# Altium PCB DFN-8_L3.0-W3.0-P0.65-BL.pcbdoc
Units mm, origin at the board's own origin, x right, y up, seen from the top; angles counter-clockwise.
Board outline 15.8 x 16.8 mm, 2 copper layers (Top Layer, Bottom Layer), stack 0 mm thick; 1 components, 0 nets, 9 pads, 0 vias.
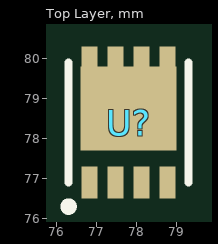
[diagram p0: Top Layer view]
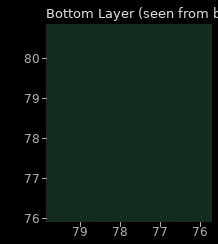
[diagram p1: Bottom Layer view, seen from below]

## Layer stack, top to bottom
Top Layer: signal copper (thickness not stored)
Bottom Layer: signal copper (thickness not stored)

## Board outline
85.655,69.85 69.85,69.85 69.85,86.655 85.655,86.655

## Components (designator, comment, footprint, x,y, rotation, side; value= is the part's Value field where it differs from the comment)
U? "" DFN-8_L3.0-W3.0-P0.65-BL 77.805,78.405 r0 top

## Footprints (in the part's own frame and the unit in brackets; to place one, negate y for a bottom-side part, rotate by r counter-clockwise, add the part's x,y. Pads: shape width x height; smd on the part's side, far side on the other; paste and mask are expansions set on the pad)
DFN-8_L3.0-W3.0-P0.65-BL [mm]
  rect 0.4x0.8 smd paste-100 mask+0.051: 1(-0.975,-1.5) 2(-0.325,-1.5) 3(0.325,-1.5) 4(0.975,-1.5) 5(0.975,1.5) 6(0.325,1.5) 7(-0.325,1.5) 8(-0.975,1.5)
  rect 2.4x2.1 smd paste-100 mask+0.051: 9(0,0.35)
  silkscreen extent -1.6,-2.2 1.5,1.5

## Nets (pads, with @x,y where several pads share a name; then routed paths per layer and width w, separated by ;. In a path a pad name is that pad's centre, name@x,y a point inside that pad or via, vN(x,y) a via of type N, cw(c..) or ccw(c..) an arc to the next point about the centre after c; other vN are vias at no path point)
pads on no net: U?.1 U?.2 U?.3 U?.4 U?.5 U?.6 U?.7 U?.8 U?.9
